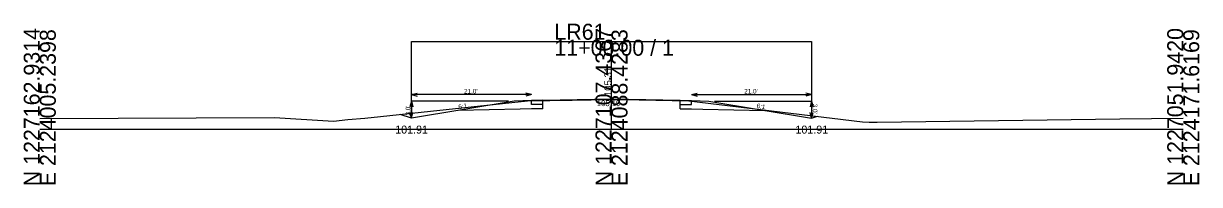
# Model space of a CAD drawing. Extents: x 2126751 to 2128979, y 1225108 to 1234639.
# Drawn here: x 2127773.8 to 2127979.4, y 1226107.5 to 1226135.7 of the extents above; entities that cross this region are included whole.
import ezdxf

# ---------------------------------------------------------------- set-up
doc = ezdxf.new("R2010")
doc.units = 0
for name, color, linetype in [('XS_CELL', 7, 'Continuous'), ('XS_M_DITCH', 7, 'Continuous'), ('XS_P_FINISHED_GRADE', 7, 'Continuous'), ('XS_P_FINISHED_GRADE_ELEV_TX', 7, 'Continuous'), ('XS_P_SUBGRADE_GRANULAR', 7, 'Continuous'), ('XS_P_SUBGRADE_LEVELING', 7, 'Continuous'), ('XS_P_SUBGRADE_PAVEMENT', 7, 'Continuous'), ('XS_P_TX_CLEARZONE', 7, 'Continuous'), ('XS_P_TX_DCH', 7, 'Continuous'), ('XS_P_TX_FS_BS', 7, 'Continuous'), ('XS_X_GROUND', 7, 'Continuous'), ('XS_X_GROUND_TX', 7, 'Continuous')]:
    doc.layers.add(name, color=color, linetype=linetype)

msp = doc.modelspace()

# ---------------------------------------------------------------- linework, layer by layer
at = {"layer": 'XS_CELL'}
for p, q in [((2127876.61, 1226117.21), (2127876.61, 1226132.85)), ((2127776.61, 1226117.21), (2127876.61, 1226117.21)), ((2127876.61, 1226117.21), (2127976.61, 1226117.21))]:
    msp.add_line(p, q, dxfattribs=at)
at = {"layer": 'XS_M_DITCH'}
for p, q in [((2127841.61, 1226119.12), (2127841.61, 1226132.52)), ((2127841.61, 1226132.52), (2127911.61, 1226132.52)), ((2127911.61, 1226132.52), (2127911.61, 1226119.12))]:
    msp.add_line(p, q, dxfattribs=at)
at = {"layer": 'XS_P_FINISHED_GRADE'}
for p, q in [((2127859.61, 1226122.12), (2127841.61, 1226119.12)), ((2127862.61, 1226122.24), (2127859.61, 1226122.12)), ((2127864.61, 1226122.28), (2127862.61, 1226122.24)), ((2127864.61, 1226122.28), (2127876.61, 1226122.52)), ((2127876.61, 1226122.52), (2127888.61, 1226122.28)), ((2127888.61, 1226122.28), (2127890.61, 1226122.24)), ((2127890.61, 1226122.24), (2127893.61, 1226122.12)), ((2127893.61, 1226122.12), (2127911.61, 1226119.12)), ((2127841.61, 1226119.12), (2127839.63, 1226119.78)), ((2127911.61, 1226119.12), (2127912.62, 1226119.46))]:
    msp.add_line(p, q, dxfattribs=at)
at = {"layer": 'XS_P_SUBGRADE_GRANULAR'}
for p, q in [((2127864.61, 1226120.78), (2127862.61, 1226120.74)), ((2127864.61, 1226120.78), (2127864.61, 1226121.53)), ((2127888.61, 1226120.78), (2127888.61, 1226121.53)), ((2127888.61, 1226120.78), (2127890.61, 1226120.74)), ((2127860.61, 1226120.7), (2127849.79, 1226120.48)), ((2127862.61, 1226120.74), (2127860.61, 1226120.7)), ((2127890.61, 1226120.74), (2127892.61, 1226120.7)), ((2127892.61, 1226120.7), (2127903.43, 1226120.48))]:
    msp.add_line(p, q, dxfattribs=at)
at = {"layer": 'XS_P_SUBGRADE_LEVELING'}
for p, q in [((2127864.61, 1226122.19), (2127869.7, 1226122.29)), ((2127864.61, 1226122.28), (2127864.61, 1226122.19)), ((2127869.7, 1226122.29), (2127876.38, 1226122.4)), ((2127876.38, 1226122.4), (2127881.46, 1226122.32)), ((2127881.46, 1226122.32), (2127888.61, 1226122.19)), ((2127888.61, 1226122.28), (2127888.61, 1226122.19))]:
    msp.add_line(p, q, dxfattribs=at)
at = {"layer": 'XS_P_SUBGRADE_PAVEMENT'}
for p, q in [((2127862.61, 1226121.49), (2127862.61, 1226122.24)), ((2127864.61, 1226121.53), (2127862.61, 1226121.49)), ((2127864.61, 1226121.53), (2127864.61, 1226122.19)), ((2127888.61, 1226121.53), (2127888.61, 1226122.19)), ((2127888.61, 1226121.53), (2127890.61, 1226121.49)), ((2127890.61, 1226121.49), (2127890.61, 1226122.24))]:
    msp.add_line(p, q, dxfattribs=at)
at = {"layer": 'XS_P_TX_CLEARZONE'}
for p, q in [((2127841.61, 1226123.24), (2127842.61, 1226123.49)), ((2127841.61, 1226123.24), (2127842.61, 1226122.99)), ((2127862.61, 1226123.24), (2127841.61, 1226123.24)), ((2127862.61, 1226123.24), (2127861.61, 1226123.49)), ((2127862.61, 1226123.24), (2127861.61, 1226122.99)), ((2127890.61, 1226123.24), (2127891.61, 1226123.49)), ((2127890.61, 1226123.24), (2127891.61, 1226122.99)), ((2127890.61, 1226123.24), (2127911.61, 1226123.24)), ((2127911.61, 1226123.24), (2127910.61, 1226123.49)), ((2127911.61, 1226123.24), (2127910.61, 1226122.99)), ((2127841.61, 1226122.12), (2127841.36, 1226121.12)), ((2127841.61, 1226122.12), (2127841.86, 1226121.12)), ((2127841.61, 1226122.12), (2127841.61, 1226119.12)), ((2127858.61, 1226122.12), (2127841.61, 1226122.12)), ((2127894.61, 1226122.12), (2127911.61, 1226122.12)), ((2127911.61, 1226122.12), (2127911.36, 1226121.12)), ((2127911.61, 1226122.12), (2127911.61, 1226119.12)), ((2127911.61, 1226122.12), (2127911.86, 1226121.12)), ((2127841.61, 1226119.12), (2127841.36, 1226120.12)), ((2127841.61, 1226119.12), (2127841.86, 1226120.12)), ((2127911.61, 1226119.12), (2127911.36, 1226120.12)), ((2127911.61, 1226119.12), (2127911.86, 1226120.12))]:
    msp.add_line(p, q, dxfattribs=at)
at = {"layer": 'XS_X_GROUND'}
for p, q in [((2127833.48, 1226119.13), (2127861.91, 1226122.14)), ((2127861.91, 1226122.14), (2127869.7, 1226122.29)), ((2127869.7, 1226122.29), (2127876.38, 1226122.4)), ((2127876.38, 1226122.4), (2127881.46, 1226122.32)), ((2127881.46, 1226122.32), (2127890.11, 1226122.17)), ((2127890.11, 1226122.17), (2127920.51, 1226118.51)), ((2127776.61, 1226119.06), (2127817.68, 1226119.23)), ((2127817.68, 1226119.23), (2127827.97, 1226118.6)), ((2127827.97, 1226118.6), (2127830.5, 1226118.88)), ((2127830.5, 1226118.88), (2127833.48, 1226119.13)), ((2127923.1, 1226118.42), (2127965.49, 1226119)), ((2127965.49, 1226119), (2127976.61, 1226119.15)), ((2127920.51, 1226118.51), (2127921.67, 1226118.42)), ((2127921.67, 1226118.42), (2127923.1, 1226118.42))]:
    msp.add_line(p, q, dxfattribs=at)

# ---------------------------------------------------------------- texts
at = {"layer": 'XS_CELL'}
for s, p in [('LR61', (2127866.61, 1226132.85)), ('11+00.00 / 1', (2127866.61, 1226130.05))]:
    msp.add_text(s, height=2.8, dxfattribs=at).set_placement(p)
for s, p in [('N 1227162.9314', (2127776.61, 1226107.21)), ('E 2124005.2398', (2127779.41, 1226107.21)), ('N 1227107.4367', (2127876.61, 1226107.21)), ('E 2124088.4283', (2127879.41, 1226107.21)), ('N 1227051.9420', (2127976.61, 1226107.21)), ('E 2124171.6169', (2127979.41, 1226107.21))]:
    msp.add_text(s, height=2.8, rotation=90, dxfattribs=at).set_placement(p)
at = {"layer": 'XS_P_FINISHED_GRADE_ELEV_TX'}
msp.add_text(' 105.31', height=1.25, rotation=90, dxfattribs=at).set_placement((2127876.61, 1226122.52))
at = {"layer": 'XS_P_TX_CLEARZONE'}
for p in [(2127850.82, 1226123.44), (2127899.82, 1226123.44)]:
    msp.add_text("21.0'", height=0.8, dxfattribs=at).set_placement(p)
for rotation, p in [(90, (2127841.41, 1226119.59)), (270, (2127911.81, 1226121.65))]:
    msp.add_text("3.0'", height=0.8, rotation=rotation, dxfattribs=at).set_placement(p)
at = {"layer": 'XS_P_TX_DCH'}
for p in [(2127838.78, 1226116.42), (2127908.78, 1226116.42)]:
    msp.add_text('101.91', height=1.4, dxfattribs=at).set_placement(p)
at = {"layer": 'XS_P_TX_FS_BS'}
for rotation, p in [(9.4623, (2127849.89, 1226120.7)), (350.5377, (2127901.95, 1226120.93))]:
    msp.add_text('6:1', height=0.8, rotation=rotation, dxfattribs=at).set_placement(p)
at = {"layer": 'XS_X_GROUND_TX'}
msp.add_text('105.19', height=1, dxfattribs=at).set_placement((2127874.05, 1226121.23))

doc.saveas('drawing.dxf')
